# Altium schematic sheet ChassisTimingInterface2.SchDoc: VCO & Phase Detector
size B; DocumentNumber: 2; Revision: C; SheetNumber: 2; SheetTotal: 12
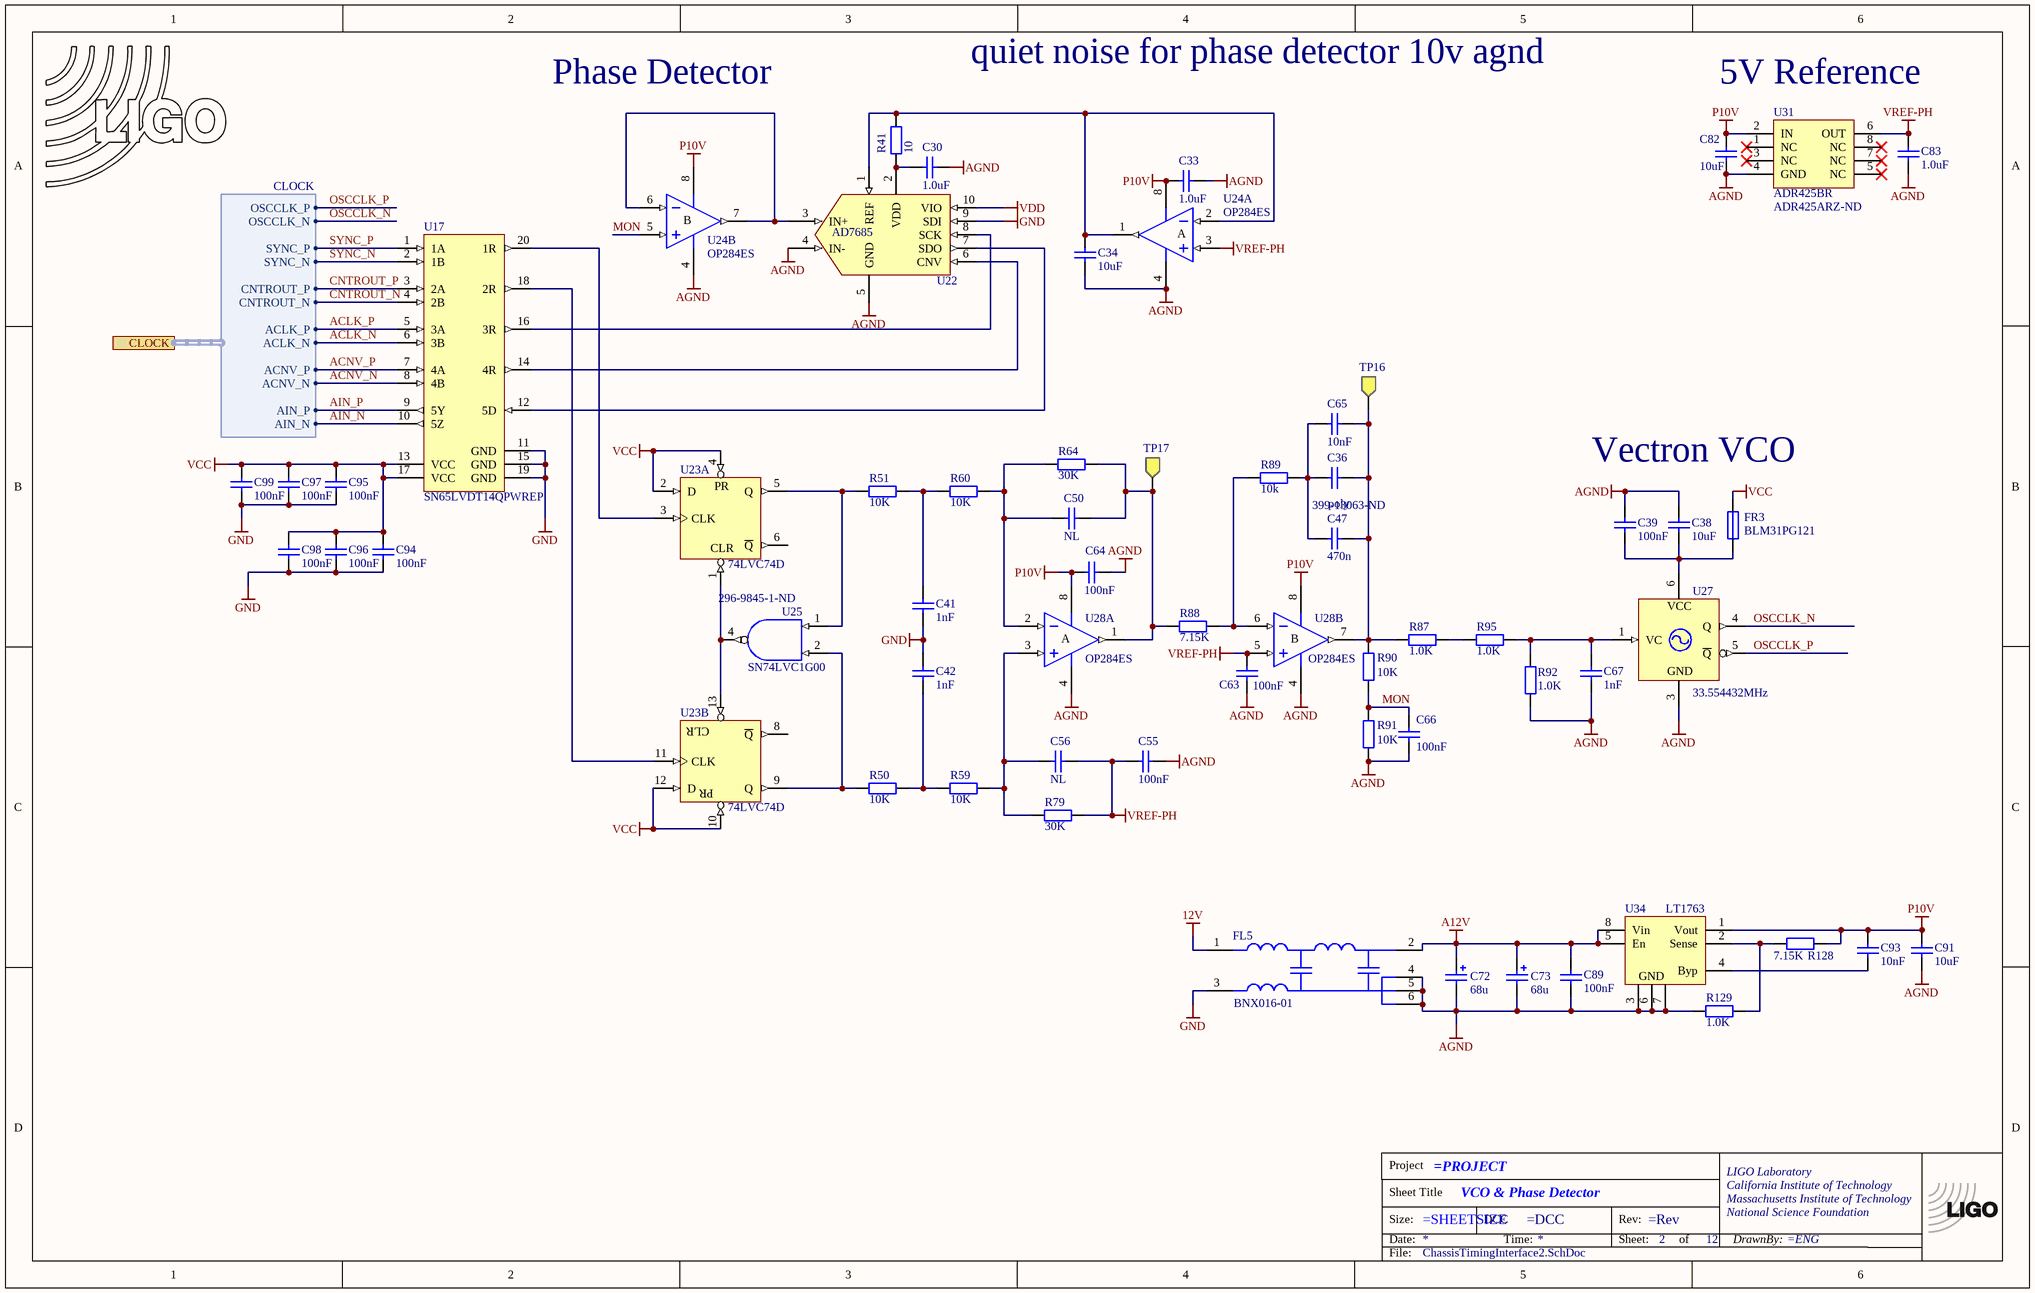
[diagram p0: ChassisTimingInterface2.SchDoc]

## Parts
*?  TitleBlock  (value not drawn)  (graphical)
C30  1.0uF  [CC1608-0603]
C33  1.0uF  [CC1608-0603]
C34  10uF  [CC2013-0805]
C36  (no value)  [CA053035]
C38  10uF  [CC2013-0805]
C39  100nF  [CC1005-0402]
C41  1nF  [CC1005-0402]
C42  1nF  [CC1005-0402]
C47  Supplier Part Number 1: 399-13063-ND  [ECQPZ120060-5.0]  (hidden comment: 470n)
C50  NL  [CC2013-0805]
C55  100nF  [CC1005-0402]
C56  NL  [CC2013-0805]
C63  100nF  [CC1005-0402]
C64  100nF  [CC1005-0402]
C65  10nF  [CC1005-0402]
C66  100nF  [CC1005-0402]
C67  1nF  [CC1005-0402]
C72  68u  [TC7343-2917]
C73  68u  [TC7343-2917]
C82  10uF  [CC2013-0805]
C83  1.0uF  [CC1608-0603]
C89  100nF  [CC1005-0402]
C91  10uF  [CC2013-0805]
C93  10nF  [CC1005-0402]
C94  100nF  [CC1005-0402]
C95  100nF  [CC1005-0402]
C96  100nF  [CC1005-0402]
C97  100nF  [CC1005-0402]
C98  100nF  [CC1005-0402]
C99  100nF  [CC1005-0402]
FL5  BNX016-01  [MURA-BNX016-01_V]
FR3  BLM31PG121  [CC3216-1206]
LOGO2  LIGO logo  [LIGO_LOGO]  (value not drawn)  (graphical)
R41  value 10  [CR1005-0402]  (hidden comment: 10.0)
R50  10K  [CR1005-0402]
R51  10K  [CR1005-0402]
R59  10K  [CR1005-0402]
R60  10K  [CR1005-0402]
R64  30K  [CR2012-0805]
R79  30K  [CR2012-0805]
R87  1.0K  [CR1608-0603]
R88  7.15K  [CR1005-0402]
R89  10k  [CR1005-0402]
R90  10K  [CR1005-0402]
R91  10K  [CR1005-0402]
R92  1.0K  [CR1608-0603]
R95  1.0K  [CR1608-0603]
R128  7.15K  [CR1005-0402]
R129  1.0K  [CR1608-0603]
TP16  Testpoint  [TP1-YLW]  (value not drawn)
TP17  Testpoint  [TP1-YLW]  (value not drawn)
U17  SN65LVDT14QPWREP  [PW0020A_N]
U22  AD7685  [TSSO3x5-G10]
U23  74LVC74D  [TSSOP14]  (parts A,B of 2)
U24  OP284ES  [SO-8_N]  (parts A,B of 2)
U25  SN74LVC1G00  Supplier Part Number 1: 296-9845-1-ND  [SO-G5/E2.4]
U27  33.554432MHz  [VECTRON_C5310]
U28  OP284ES  [SO-8_N]  (parts A,B of 2)
U31  ADR425BR  Supplier Part Number 1: ADR425ARZ-ND  [SO-G8]
U34  LT1763  [SO-G8]

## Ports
CLOCK (harness CLOCK)

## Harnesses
CLOCK: OSCCLK_N, OSCCLK_P, CNTROUT_N, CNTROUT_P, SYNC_N, SYNC_P, ACLK_P, ACLK_N, ACNV_P, ACNV_N, AIN_P, AIN_N

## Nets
12V: FL5.1(B)
A12V: C72.1 C73.1 C89.2 FL5.2(CB) U34.5(En) U34.8(Vin)
AGND: C30.1 C33.1 C34.2 C38.1 C39.1 C55.1 C63.1 C64.1 C66.1 C67.2 C72.2 C73.2 C82.2 C83.1 C89.1 C91.2 FL5.4(CG) FL5.5(CG) FL5.6(CG) R91.2 R92.2 R129.2 U22.4(IN-) U22.5(GND) U24.4(V-) U27.3(GND) U28.4(V-) U31.4(GND) U34.3(GND) U34.6(GND) U34.7(GND)
GND: C41.2 C42.1 C94.1 C95.1 C96.1 C97.1 C98.1 C99.1 FL5.3(PSG) U17.11(GND) U17.15(GND) U17.19(GND) U22.9(SDI) U23.7(GND) U25.3(GND)
P10V: C33.2 C64.2 C82.1 C91.1 C93.1 R128.2 U24.8(V+) U28.8(V+) U31.2(IN) U34.1(Vout)
VCC: C94.2 C95.2 C96.2 C97.2 C98.2 C99.2 FR3.2 U17.13(VCC) U17.17(VCC) U23.2(D) U23.4(PR) U23.10(PR) U23.12(D) U23.14(VCC) U25.5(VCC)
VDD: U22.10(VIO)
VREF-PH: C55.2 C56.1 C63.2 C83.2 R79.2 U24.3(IN+) U28.5(IN+) U31.6(OUT)
ACLK_N: U17.6(3B) ; port CLOCK.ACLK_N
ACLK_P: U17.5(3A) ; port CLOCK.ACLK_P
ACNV_N: U17.8(4B) ; port CLOCK.ACNV_N
ACNV_P: U17.7(4A) ; port CLOCK.ACNV_P
AIN_N: U17.10(5Z) ; port CLOCK.AIN_N
AIN_P: U17.9(5Y) ; port CLOCK.AIN_P
CNTROUT_N: U17.4(2B) ; port CLOCK.CNTROUT_N
CNTROUT_P: U17.3(2A) ; port CLOCK.CNTROUT_P
MON: C66.2 R90.2 R91.1 U24.5(IN+)
OSCCLK_N: U27.4(Q) ; port CLOCK.OSCCLK_N
OSCCLK_P: U27.5(~{Q}) ; port CLOCK.OSCCLK_P
SYNC_N: U17.2(1B) ; port CLOCK.SYNC_N
SYNC_P: U17.1(1A) ; port CLOCK.SYNC_P
NetC30_2: C30.2 R41.1 U22.2(VDD)
NetC34_1: C34.1 R41.2 U22.1(REF) U24.1(OUT) U24.2(IN-)
NetC36_1: C36.1 C47.1 C65.2 R89.2
NetC36_2: C36.2 C47.2 C65.1 R87.2 R90.1 TP16.1 U28.7(OUT)
NetC38_2: C38.2 C39.2 FR3.1 U27.6(VDD)
NetC41_1: C41.1 R51.2 R60.1
NetC42_2: C42.2 R50.2 R59.1
NetC50_1: C50.1 R64.2 R88.1 TP17.1 U28.1(OUT)
NetC50_2: C50.2 R60.2 R64.1 U28.2(IN-)
NetC56_2: C56.2 R59.2 R79.1 U28.3(IN+)
NetC67_1: C67.1 R92.1 R95.1 U27.1(VC)
NetC93_2: C93.2 U34.4(Byp)
NetR50_1: R50.1 U23.9(Q) U25.2
NetR51_1: R51.1 U23.5(Q) U25.1
NetR87_1: R87.1 R95.2
NetR88_2: R88.2 R89.1 U28.6(IN-)
NetR128_1: R128.1 R129.1 U34.2(Sense)
NetU17_12: U17.12(5D) U22.7(SDO)
NetU17_14: U17.14(4R) U22.6(CNV)
NetU17_16: U17.16(3R) U22.8(SCK)
NetU17_18: U17.18(2R) U23.11(CLK)
NetU17_20: U17.20(1R) U23.3(CLK)
NetU22_3: U22.3(IN+) U24.6(IN-) U24.7(OUT)
NetU23_1: U23.1(CLR) U23.13(CLR) U25.4

Not connected (* = marked no-connect by the designer): U23 6(~{Q}) 8(~{Q}); U27 2(NC); U31 1(NC)* 3(NC)* 5(NC)* 7(NC)* 8(NC)*

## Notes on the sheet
- Phase Detector
- quiet noise for phase detector 10v agnd
- 5V Reference
- poly
- Vectron VCO

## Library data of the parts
C30 C33 C83 = ChipCap: C0603 1.0uF; Part Number: 1276-1184-1-ND; Tolerance: 10%
C34 C38 C82 C91 = ChipCap: C0805 10uF; Part Number: 1276-6454-1-ND; Tolerance: 10%
C36 = CapFilmAxial: Film Capacitor, axial lead; Part Number: MCO2B474G; Tolerance: 2%
C39 C55 C63 C64 C66 C89 C94-C99 = ChipCap: C0402 0.1uF; Part Number: 1276-6720-1-ND; Tolerance: 10%
C41 C42 C67 = ChipCap: C0402 1.0nF; Part Number: 1292-1246-1-ND; Tolerance: 10%
C47 = CapPolypropylene ECQPZ: Polypropylene Film Capacitor, radial lead; Tolerance: 2%
C50 C56 = ChipCap: Capacitor, surface mount
C65 C93 = ChipCap: C0402 0.01uF; Part Number: 311-1349-1-ND; Tolerance: 10%
C72 C73 = ChipTantalum: Tantalum capacitor, surface mount; Part Number: 399-3908-1-ND; Tolerance: 20%
FL5 = CMP-2000-05960-1: Block Type EMIFIL(R) Reference Specification, 15 A, 25 V, -40 to 125 degC, 6-Pin THD, RoHS, Bulk; Part Number: 490-5055-ND
FR3 = BLM31PG121SN1: ferrite bead, 120Ohm at 100MHz, 1206; Part Number: 490-1056-1-ND
LOGO2 = LIGO_logo
R41 = ChipRes1: R0402 10; Part Number: A127127CT-ND; Tolerance: 0.1%
R50 R51 R59 R60 R89-R91 = ChipRes1: R0402 10k; Part Number: RR05P10.0KDCT-ND; Tolerance: 0.1%
R64 R79 = ChipRes1: R0805 30k; Part Number: RR12P30.0KDCT-ND; Tolerance: 0.1%
R87 R92 R95 R129 = ChipRes1: R0603 1.0k; Part Number: RR08P1.0KDCT-ND; Tolerance: 0.1%
R88 R128 = ChipRes1: R0402 7.15k; Part Number: YAG1478CT-ND; Tolerance: 0.1%
TP16 TP17 = TP_SIGNAL: Testpoint, yellow; Part Number: 36-5004-ND
U17 = CMP-0327-00205-3: 125 Mbps Enhanced Product Memorystick? Interconnect Extender Chipset with LVDS and LVTTL, 1 Tx and 4 Rx, -55 to +125 degC, 20-pin TSSOP (PW), Green (RoHS & no Sb/Br); Part Number: 296-19499-1-ND
U22 = AD7685: 16 bit ADC, 250kSPS, pseudo differential, serial; Part Number: AD7685ARMZRL7CT-ND
U23 = 74F74PC: Dual D-Type Positive Edge-Triggered Flip-Flop; Part Number: 296-1240-5-ND
U24 U28 = OP284ES: Precision Rail-to-Rail Input and Output Operational Amplifier; Part Number: OP284ESZ-REEL7TR-ND
U27 = VECTRON_C5310: Voltage controlled crystal oscillator; Part Number: C5310-D105-SV033-RFL-B1-67.108864MHz
U31 = ADR292ER: Low-Noise Micropower Precision Voltage Reference
U34 = LT1763: Positive voltage regulator; Part Number: LT1763CS8#PBF-ND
